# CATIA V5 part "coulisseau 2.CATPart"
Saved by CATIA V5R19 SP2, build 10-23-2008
Part number: coulisseau 2
Publications: "Esquisse.1"
Bounding box of the stored display mesh (mm): x -65 to -60, y 5 to 15, z -4.382 to 4.618
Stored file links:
  C:\Users\Thinkmotion2\Desktop\Pack 1\IAO_2010_1396_fvigouroux\vigouroux\vigouroux\coulisseau 2.CATPart
  C:\Users\Thinkmotion2\Desktop\Pack 1\IAO_2010_1396_fvigouroux\vigouroux\vigouroux\mecanisme IAO.CATProduct
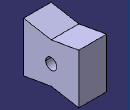
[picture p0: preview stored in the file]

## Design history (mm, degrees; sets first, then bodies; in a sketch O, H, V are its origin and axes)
External parameters (linked from other documents)
  `External.hauteur du coulisseau` = 5 mm
  `External.profondeur rainure disque` = 5 mm
Set1
  Plane1: linked copy from another document
  Point1: linked copy from another document
  Plane2: linked copy from another document
Body1 (main body)
  Sketch1 on Plane1, origin (-60, 0, 0), H (0, 1, 0), V (0, 0, 1)
    point P1 (10, -3.5)
    line L1 (10, -3.5) -> (5, -4.3816)
    point P2 (5, -4.3816)
    line L2 (5, -4.3816) -> (5, 4.6184)
    point P3 (5, 4.6184)
    line L3 (5, 4.6184) -> (10, 3.7367)
    point P4 (10, 3.7367)
    axis line L4 (10, 20.8652) -> (10, 3.0844)
    reference projected point E1 (10, 0) from Point1
    point P7 (15, -4.3816)
    point P8 (10, -3.5)
    line L5 (10, -3.5) -> (15, -4.3816)
    point P9 (15, 4.6184)
    point P10 (15, -4.3816)
    line L6 (15, -4.3816) -> (15, 4.6184)
    point P11 (10, 3.7367)
    point P12 (15, 4.6184)
    line L7 (15, 4.6184) -> (10, 3.7367)
    circle A1 centre (10, 0) radius 1
    point P13 (10, 0)
    reference projected point E2 (10, 0) from Point1
    length L2 = 9
    distance L4 E1 = 0
    distance P1 L4 = 0
    distance P4 L4 = 0
    angle L3 L2 = 80
    angle L1 L2 = 80
    distance L2 L4 = 5 {= `External.hauteur du coulisseau`}
    radius A1 = 1
    distance P1 P13 = 3.5
    distance P13 E2 = 0
    vertical: L2 V, L4 V
    symmetry: P2 P7 L4, P1 P8 L4, L1 L5 L4, P3 P9 L4, P2 P10 L4, L2 L6 L4, P4 P11 L4, P3 P12 L4, L3 L7 L4
    coincidence: P13 L4
  Pad1: profile Sketch1, direction (-1, 0, 0), length 5 {= `External.profondeur rainure disque`}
